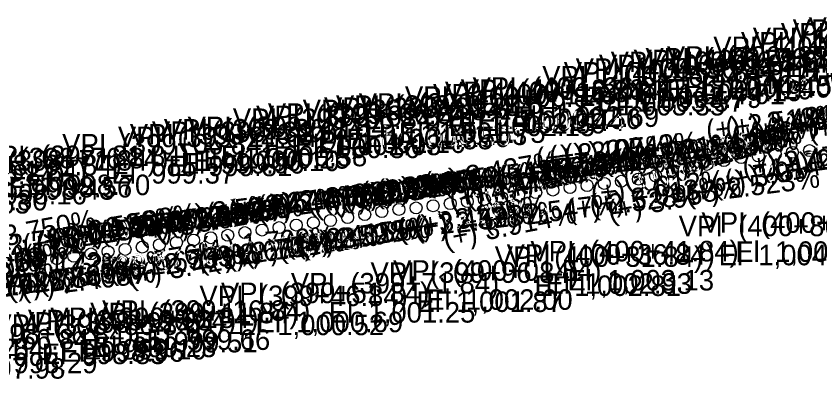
# Model space of a CAD drawing. Extents: x 16972137 to 16976737, y 12558490 to 12559551.
# Drawn here: x 16974247.9 to 16974482.8, y 12558895.6 to 12559001.6 of the extents above; entities that cross this region are included whole.
import ezdxf

# ---------------------------------------------------------------- set-up
doc = ezdxf.new("R2010")
doc.units = 0
doc.layers.add('RD_DDB_GradeTX', color=7, linetype='Continuous')
doc.layers.add('RD_DDB_PI', color=7, linetype='Continuous')

msp = doc.modelspace()

# ---------------------------------------------------------------- linework, layer by layer
at = {"layer": 'RD_DDB_PI'}
for centre in [(16974474.74, 12558961.81), (16974479.74, 12558962.31), (16974459.74, 12558960.25), (16974464.74, 12558960.78), (16974469.74, 12558961.3), (16974444.74, 12558957.18), (16974449.74, 12558958.28), (16974454.74, 12558959.38), (16974434.74, 12558954.95), (16974439.74, 12558956.07), (16974419.74, 12558952.74), (16974424.74, 12558953.35), (16974429.74, 12558953.98), (16974399.74, 12558950.05), (16974404.74, 12558950.8), (16974409.74, 12558951.5), (16974414.74, 12558952.12), (16974384.74, 12558948.07), (16974389.74, 12558948.67), (16974394.74, 12558949.3), (16974364.74, 12558945.57), (16974369.74, 12558946.2), (16974374.74, 12558946.83), (16974379.74, 12558947.45), (16974349.74, 12558943.62), (16974354.74, 12558944.48), (16974359.74, 12558945.12), (16974334.74, 12558941.24), (16974339.74, 12558941.9), (16974344.74, 12558942.76), (16974314.74, 12558938.35), (16974319.74, 12558939.1), (16974324.74, 12558939.83), (16974329.74, 12558940.55), (16974299.74, 12558936.18), (16974304.74, 12558936.87), (16974309.74, 12558937.59), (16974284.74, 12558934.12), (16974289.74, 12558934.8), (16974294.74, 12558935.48), (16974264.74, 12558931.47), (16974269.74, 12558932.13), (16974274.74, 12558932.8), (16974279.74, 12558933.45), (16974249.74, 12558929.2), (16974254.74, 12558930.1), (16974259.74, 12558930.78)]:
    msp.add_circle(centre, 1.75, dxfattribs=at)

# ---------------------------------------------------------------- texts
at = {"layer": 'RD_DDB_GradeTX'}
for s, rotation, p in [('(+) 4.409%', 12.4309, (16974462.99, 12558964.28)), ('(+) 4.378%', 12.3465, (16974467.77, 12558965.3)), ('(+) 3.504%', 9.9364, (16974472.64, 12558965.56)), ('(+) 2.513%', 7.1606, (16974449.87, 12558965.17)), ('(+) 2.491%', 7.1005, (16974455.51, 12558965.94)), ('(+) 4.439%', 12.5145, (16974457.69, 12558963.13)), ('(+) 2.105%', 6.007, (16974479.61, 12558965.36)), ('(+) 4.336%', 12.2337, (16974444.25, 12558958.54)), ('(+) 5.267%', 14.7548, (16974435.21, 12558953.38)), ('(+) 2.433%', 6.9366, (16974437.53, 12558957.92)), ('(+) 5.245%', 14.6942, (16974439.79, 12558954.65)), ('(+) 2.105%', 6.007, (16974400.08, 12558956.99)), ('(+) 2.074%', 5.9202, (16974403.96, 12558957.49)), ('(+) 2.043%', 5.8332, (16974408.36, 12558958.04)), ('(+) 2.981%', 8.4785, (16974419.61, 12558956.05)), ('(+) 2.788%', 7.9364, (16974423.2, 12558956.4)), ('(+) 5.312%', 14.874, (16974426.15, 12558950.84)), ('(+) 2.497%', 7.1155, (16974428.51, 12558956.86)), ('(+) 5.290%', 14.8148, (16974429.94, 12558951.92)), ('(+) 2.465%', 7.0262, (16974433.11, 12558957.41)), ('(+) 2.825%', 8.0388, (16974470.06, 12558954.7)), ('(+) 3.504%', 9.9364, (16974393.92, 12558951.77)), ('(+) 2.415%', 6.8845, (16974404.65, 12558953.49)), ('(+) 4.470%', 12.5977, (16974455.76, 12558950.43)), ('(+) 2.470%', 7.0402, (16974460.51, 12558954.53)), ('(+) 2.737%', 7.7918, (16974465.63, 12558954.36)), ('(+) 3.437%', 9.7498, (16974367.78, 12558949.77)), ('(+) 4.378%', 12.3465, (16974389.74, 12558948.22)), ('(+) 2.514%', 7.1653, (16974389.62, 12558951.73)), ('(+) 2.481%', 7.072, (16974394.75, 12558952.34)), ('(+) 2.448%', 6.9784, (16974398.23, 12558952.74)), ('(+) 3.914%', 11.0723, (16974451.68, 12558949.1)), ('(+) 2.542%', 7.2446, (16974372.74, 12558949.79)), ('(+) 4.470%', 12.5977, (16974375.19, 12558944.72)), ('(+) 4.439%', 12.5145, (16974379.71, 12558945.82)), ('(+) 1.799%', 5.1409, (16974380.57, 12558950)), ('(+) 4.409%', 12.4309, (16974384.98, 12558947.08)), ('(+) 2.854%', 8.1227, (16974342.89, 12558945.45)), ('(+) 2.788%', 7.9364, (16974344.01, 12558945.36)), ('(+) 2.766%', 7.8748, (16974348.44, 12558946.16)), ('(+) 2.497%', 7.1155, (16974349.17, 12558946.96)), ('(+) 2.655%', 7.562, (16974352.83, 12558946.66)), ('(+) 2.465%', 7.0262, (16974353.75, 12558947.63)), ('(+) 2.012%', 5.7458, (16974416.15, 12558946.87)), ('(+) 2.523%', 7.1887, (16974443.84, 12558946.68)), ('(+) 2.996%', 8.5208, (16974333.2, 12558944.15)), ('(+) 3.013%', 8.566, (16974335.08, 12558943.35)), ('(+) 2.942%', 8.3668, (16974337.86, 12558944.79)), ('(+) 2.981%', 8.4785, (16974340.54, 12558944.26)), ('(+) 3.013%', 8.566, (16974415.92, 12558943.39)), ('(+) 3.958%', 11.1934, (16974421.45, 12558941.6)), ('(+) 2.514%', 7.1653, (16974310.28, 12558941.75)), ('(+) 2.481%', 7.072, (16974315.39, 12558942.49)), ('(+) 2.776%', 7.9034, (16974318.61, 12558941.83)), ('(+) 2.448%', 6.9784, (16974318.86, 12558943.02)), ('(+) 2.528%', 7.2053, (16974409.13, 12558942.05)), ('(+) 2.542%', 7.2446, (16974293.42, 12558939.71)), ('(+) 2.547%', 7.2582, (16974303.95, 12558940.85)), ('(+) 3.462%', 9.8204, (16974364.7, 12558937.08)), ('(+) 2.547%', 7.2582, (16974384.78, 12558939.05)), ('(+) 2.665%', 7.5888, (16974283.06, 12558936.94)), ('(+) 3.462%', 9.8204, (16974283.9, 12558935.27)), ('(+) 2.645%', 7.5339, (16974288.06, 12558937.58)), ('(+) 3.437%', 9.7498, (16974289.01, 12558936.23)), ('(+) 2.625%', 7.4787, (16974292.72, 12558938.18)), ('(+) 3.429%', 9.7277, (16974359.69, 12558936.19)), ('(+) 2.523%', 7.1887, (16974364.5, 12558936.68)), ('(+) 3.750%', 10.6204, (16974232.74, 12558932.08)), ('(+) 3.526%', 9.9989, (16974257.4, 12558933.61)), ('(+) 3.508%', 9.9478, (16974262.53, 12558934.49)), ('(+) 2.854%', 8.1227, (16974263.74, 12558934.16)), ('(+) 2.766%', 7.8748, (16974269.24, 12558935.21)), ('(+) 2.732%', 7.779, (16974272.69, 12558935.58)), ('(+) 2.433%', 6.9366, (16974359.6, 12558936.35)), ('(+) 3.914%', 11.0723, (16974373.26, 12558933.75)), ('(+) 3.015%', 8.5738, (16974250.25, 12558931.66)), ('(+) 2.996%', 8.5208, (16974254.14, 12558932.3)), ('(+) 2.942%', 8.3668, (16974258.77, 12558933.16)), ('(+) 2.415%', 6.8845, (16974326.7, 12558931.99)), ('(+) 2.528%', 7.2053, (16974329.8, 12558932.02)), ('(+) 3.015%', 8.5738, (16974331.09, 12558931.71)), ('(+) 2.795%', 7.9563, (16974234.02, 12558930.02)), ('(+) 1.799%', 5.1409, (16974301.99, 12558930.89)), ('(+) 2.795%', 7.9563, (16974314.86, 12558929.2)), ('(+) 2.889%', 8.2204, (16974324.71, 12558930.66)), ('(+) 6.467%', 17.9175, (16974231.2, 12558921.52)), ('(+) 2.671%', 7.6059, (16974301.58, 12558927.29)), ('(+) 2.704%', 7.6996, (16974304.95, 12558927.77)), ('(+) 2.728%', 7.7659, (16974309.6, 12558928.42)), ('(+) 6.068%', 16.8769, (16974225.76, 12558919.49)), ('(+) 3.576%', 10.1379, (16974270.02, 12558923.69)), ('(+) 2.753%', 7.8386, (16974279.44, 12558924.41)), ('(+) 1.806%', 5.1588, (16974215.16, 12558925.75)), ('(-) 1.172%', 356.6475, (16974242.24, 12558928.28)), ('(-) 1.421%', 355.9359, (16974247.08, 12558927.72)), ('(+) 3.589%', 10.1734, (16974254.74, 12558920.99)), ('(+) 2.655%', 7.562, (16974275.14, 12558924.25)), ('(+) 3.429%', 9.7277, (16974280.92, 12558922.68)), ('(+) 4.694%', 13.2093, (16974220.75, 12558917.04)), ('(+) 2.728%', 7.7659, (16974230.38, 12558917.62)), ('(+) 2.776%', 7.9034, (16974241.07, 12558918.95)), ('(+) 2.889%', 8.2204, (16974245.59, 12558919.23)), ('(+) 2.408%', 6.8641, (16974249.56, 12558919.27)), ('(+) 2.625%', 7.4787, (16974215, 12558915.88)), ('(+) 2.671%', 7.6059, (16974222.32, 12558916.71)), ('(+) 2.704%', 7.6996, (16974225.71, 12558917.06))]:
    msp.add_text(s, height=6, rotation=rotation, dxfattribs=at).set_placement(p)
at = {"layer": 'RD_DDB_PI'}
for s, p in [('VPI  (401+21.84)', (16974479.46, 12558995.29)), ('VPI  (401+11.84)', (16974471.35, 12558993.58)), ('VPI  (401+16.84)', (16974474.81, 12558994.66)), ('VPI  (401+01.84)', (16974459.69, 12558990.95)), ('VPI  (401+06.84)', (16974463.16, 12558992.27)), ('VPI  (400+96.84)', (16974451.62, 12558989.63)), ('VPI  (400+71.84)', (16974428.33, 12558985.78)), ('VPI  (400+76.84)', (16974431.8, 12558986.3)), ('VPI  (400+81.84)', (16974438.04, 12558986.81)), ('VPI  (400+56.84)', (16974411.39, 12558983.28)), ('VPI  (400+61.84)', (16974418.16, 12558984.38)), ('VPI  (400+66.84)', (16974421.62, 12558985.25)), ('El  1,005.59', (16974472.81, 12558983.77)), ('El  1,005.85', (16974477.72, 12558985.08)), ('VPI  (400+46.84)', (16974401.62, 12558981.07)), ('VPI  (400+51.84)', (16974407.92, 12558982.18)), ('El  1,005.06', (16974462.93, 12558981.13)), ('El  1,005.33', (16974467.25, 12558982.45)), ('VPI  (400+16.84)', (16974373.16, 12558976.5)), ('VPI  (400+21.84)', (16974377.8, 12558977.12)), ('VPI  (400+26.84)', (16974381.27, 12558977.74)), ('El  1,004.19', (16974434.82, 12558976.75)), ('El  1,004.29', (16974437.93, 12558977.28)), ('El  1,004.40', (16974443.17, 12558977.8)), ('El  1,004.50', (16974447.93, 12558978.31)), ('VPI  (400+06.84)', (16974361.5, 12558975.05)), ('VPI  (400+11.84)', (16974369.69, 12558975.8)), ('El  1,003.57', (16974417.81, 12558973.68)), ('El  1,003.79', (16974423.05, 12558974.78)), ('El  1,004.01', (16974429.7, 12558975.88)), ('VPI  (399+81.84)', (16974337.86, 12558971.83)), ('VPI  (399+86.84)', (16974341.33, 12558972.45)), ('VPI  (399+91.84)', (16974347.98, 12558973.07)), ('El  1,003.35', (16974412.25, 12558972.57)), ('VPI  (399+61.84)', (16974317.98, 12558969.48)), ('VPI  (399+66.84)', (16974321.44, 12558970.12)), ('VPI  (399+76.84)', (16974331.62, 12558971.2)), ('El  1,002.69', (16974392.93, 12558969.24)), ('VPI  (399+56.84)', (16974311.21, 12558968.62)), ('El  1,002.30', (16974377.4, 12558967.3)), ('El  1,002.44', (16974382.93, 12558968)), ('El  1,002.56', (16974387.69, 12558968.62)), ('VPI  (399+31.84)', (16974287.57, 12558964.83)), ('VPI  (399+36.84)', (16974291.03, 12558965.55)), ('VPI  (399+41.84)', (16974297.98, 12558966.24)), ('El  1,001.75', (16974359.79, 12558964.57)), ('El  1,002.15', (16974374.26, 12558966.55)), ('VPI  (399+21.84)', (16974277.63, 12558963.35)), ('VPI  (399+26.84)', (16974281.09, 12558964.1)), ('El  1,001.38', (16974344.32, 12558962.7)), ('El  1,001.50', (16974349.47, 12558963.33)), ('El  1,001.63', (16974354.44, 12558963.95)), ('VPI  (399+06.84)', (16974261.33, 12558961.18)), ('El  1,000.86', (16974323.05, 12558960.12)), ('El  1,001.03', (16974329.32, 12558960.98)), ('El  1,001.16', (16974336.36, 12558961.62)), ('VPI  (398+81.84)', (16974237.74, 12558957.8)), ('El  1,000.38', (16974307.66, 12558957.74)), ('VPI  (398+61.84)', (16974217.86, 12558955.1)), ('VPI  (398+71.84)', (16974228.04, 12558956.47)), ('VPI  (398+76.84)', (16974231.5, 12558957.13)), ('El  999.81', (16974292.42, 12558954.85)), ('El  999.96', (16974296, 12558955.6)), ('El  1,000.10', (16974299.58, 12558956.33)), ('El  1,000.25', (16974302.61, 12558957.05)), ('VPI  (398+51.84)', (16974207.63, 12558953.33)), ('El  999.37', (16974275.76, 12558952.68)), ('VPI  (398+46.84)', (16974201.33, 12558952.44)), ('El  998.43', (16974240.5, 12558947.97)), ('El  998.56', (16974245.65, 12558948.63)), ('El  998.70', (16974250.94, 12558949.3)), ('El  998.16', (16974232.42, 12558946.6)), ('El  997.63', (16974215.79, 12558943.94)), ('El  997.80', (16974220.94, 12558944.83)), ('VPI  (400+86.84)', (16974441.5, 12558937.31)), ('VPI  (400+91.84)', (16974448.16, 12558938.3)), ('VPI  (400+41.84)', (16974398.16, 12558929.95)), ('El  1,004.80', (16974458.05, 12558929.8)), ('VPI  (400+31.84)', (16974387.74, 12558928.35)), ('VPI  (400+36.84)', (16974391.21, 12558928.98)), ('El  1,004.60', (16974453.17, 12558928.81)), ('VPI  (400+01.84)', (16974358.04, 12558924.3)), ('VPI  (399+96.84)', (16974351.44, 12558923.67)), ('VPI  (399+71.84)', (16974328.16, 12558920.57)), ('El  1,002.81', (16974399.35, 12558919.85)), ('El  1,002.93', (16974402.55, 12558920.48)), ('El  1,003.13', (16974409.02, 12558921.45)), ('VPI  (399+51.84)', (16974307.74, 12558917.76)), ('VPI  (399+46.84)', (16974301.44, 12558916.9)), ('El  1,001.87', (16974364.88, 12558915.17)), ('El  1,002.00', (16974367.69, 12558915.8)), ('VPI  (399+16.84)', (16974272.98, 12558912.59)), ('VPI  (399+01.84)', (16974257.86, 12558910.48)), ('VPI  (399+11.84)', (16974269.51, 12558911.87)), ('El  1,001.25', (16974339.26, 12558912.07)), ('VPI  (398+86.84)', (16974241.21, 12558908.45)), ('VPI  (398+91.84)', (16974247.86, 12558909.12)), ('VPI  (398+96.84)', (16974251.33, 12558909.8)), ('El  1,000.52', (16974312.61, 12558908.4)), ('El  1,000.69', (16974318.17, 12558909.26)), ('VPI  (398+66.84)', (16974221.33, 12558905.78)), ('VPI  (398+56.84)', (16974211.09, 12558904.2)), ('El  999.51', (16974282.3, 12558903.37)), ('El  999.66', (16974286, 12558904.09)), ('VPI  (398+36.84)', (16974190.91, 12558900.95)), ('VPI  (398+41.84)', (16974197.86, 12558901.55)), ('El  999.10', (16974267.42, 12558901.3)), ('El  999.23', (16974270.26, 12558901.98)), ('El  998.83', (16974255.38, 12558899.95)), ('El  998.96', (16974260.88, 12558900.62)), ('El  998.29', (16974235.53, 12558897.28)), ('El  997.98', (16974226.09, 12558895.7))]:
    msp.add_text(s, height=6, dxfattribs=at).set_placement(p)

doc.saveas('drawing.dxf')
